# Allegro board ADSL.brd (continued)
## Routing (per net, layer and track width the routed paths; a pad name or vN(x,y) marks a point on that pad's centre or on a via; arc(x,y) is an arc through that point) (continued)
EJTAG_TDI: length 5.1
  TOP w0.152: U1.52 63.77,20.64 63.69,20.56 63.69,18.71 R388.2
EJTAG_TDO: length 6.6
  TOP w0.152: U1.49 62.27,17.42 R387.2 R365.2 R366.2
EJTAG_TMS: length 1.9
  TOP w0.152: R380.2 62.77,20.13 U1.50
EJTAG_TRST: length 4.8
  TOP w0.152: U1.51 63.27,20.7 63.39,20.59 63.39,18.53 63.88,18.03 R364.2
ETHERNET: length 46.2
  TOP w0.152: v2(57.02,3.3) 57.43,2.9 58.78,2.9 59.69,3.81 62.08,3.81 62.99,2.9 66.78,2.9 LED4.2 ; v2(55.63,22.35) 55.63,22.86 56.92,24.16 56.92,33.36 56.39,33.89 U1.16
  BOTTOM w0.152: v2(57.02,3.3) 57.02,4.7 56.26,5.46 56.26,21.72 v2(55.63,22.35)
FFRING: length 12.7
  TOP w0.254: R385.2 105.03,49.38 R381.2 ; R381.2 R382.2 ; R381.2 104.67,49.74 104.67,51.3 R427.1
  TOP w0.508: R427.1 104.8,52.39 104.8,53.11 103.8,54.1 100.71,54.1 100.32,54.5 T5.6
FFTIP: length 13.5
  TOP w0.254: R382.1 R381.1 ; R381.1 104.27,49.62 104.27,51.27 R428.1 ; R381.1 104.02,49.38 R384.2
  TOP w0.508: T5.7 98.62,54.36 99.53,53.44 103.53,53.44 104.14,52.83 104.14,52.42 R428.1
FL_A15: length 43.2
  TOP w0.152: U29.2 88.44,51.06 88.46,51.04 89.32,50.18 89.32,46.21 87.96,44.86 77.98,44.86 75.93,46.9 73.87,46.9 72.77,45.8 72.77,44.88 72.28,44.39 U1.112
FL_A16: length 43.2
  TOP w0.152: U29.1 88.94,66.74 88.74,66.55 88.74,51.47 89.62,50.59 89.62,45.98 88.2,44.55 77.85,44.55 75.81,46.6 74,46.6 73.15,45.75 73.15,44.83 72.97,44.65 72.78,44.46 U1.111
FL_A17: length 22.6
  TOP w0.152: U29.48 88.94,46.26 87.86,45.19 78.13,45.19 75.88,47.43 v2(74.3,47.43) ; U1.110 73.28,44.45 73.79,44.96 v2(73.79,45.47)
  BOTTOM w0.152: v2(74.3,47.43) 73.79,46.93 v2(73.79,45.47)
FL_A18: length 49.2
  TOP w0.152: U29.17 v2(80.93,62.45) ; U1.108 76.65,41.39 77.39,42.14 81.15,42.14 82.04,43.03 88.83,43.03 91.15,45.34 91.15,61.24 v2(90.92,61.47)
  BOTTOM w0.152: v2(90.92,61.47) 90.28,62.1 81.24,62.1 80.93,62.41 v2(80.93,62.45)
FL_A19: length 49.5
  TOP w0.152: U1.107 76.58,40.89 77.52,41.83 81.28,41.83 82.17,42.72 88.96,42.72 91.45,45.22 91.45,61.84 v2(91.06,62.23) ; v2(81.47,62.99) 81.43,63.03 U29.16
  BOTTOM w0.152: v2(81.47,62.99) 82.05,62.41 90.88,62.41 v2(91.06,62.23)
FL_A20: length 49.3
  TOP w0.152: U1.106 76.59,40.39 77.72,41.53 81.41,41.53 82.3,42.42 89.08,42.42 91.75,45.09 91.75,63.63 89.41,65.97 89.41,69.34 87.79,70.96 R415.1 85.08,70.97 R416.2
FL_A21: length 51.1
  TOP w0.152: U1.104 74.91,39.39 74.78,39.52 74.78,41.61 75.61,42.44 81.03,42.44 81.92,43.33 88.7,43.33 90.84,45.47 90.84,51.69 90.38,52.15 90.38,62.32 90.87,62.81 90.87,63.56 v2(90.42,64.01) ; v2(84.2,64.01) 83.68,64.53 83.68,66.03 84.43,66.78 U29.10
  BOTTOM w0.152: v2(90.42,64.01) 89.89,64.54 88.42,64.54 87.88,64.01 v2(84.2,64.01)
FL_A22: length 53.1
  TOP w0.152: v2(82.58,62.94) 82.58,63.26 82.57,63.27 82.57,66.44 82.94,66.81 U29.13 ; U1.102 74.89,38.39 74.48,38.81 74.48,41.76 75.46,42.75 80.9,42.75 81.79,43.64 88.58,43.64 90.54,45.6 90.54,51.31 90.08,51.77 90.08,62.87 v2(90.34,63.13)
  BOTTOM w0.152: v2(90.34,63.13) 89.93,62.71 82.8,62.71 v2(82.58,62.94)
FL_CS0: length 22.6
  TOP w0.152: v2(73.94,40.89) 73.39,40.34 73.39,39.77 73.85,39.31 73.85,35.49 74.46,34.89 U1.95 76.71,34.89 77.62,35.8 R373.2 R372.2 ; U29.26 77.93,46.41 v2(78.11,46.23)
  BOTTOM w0.152: v2(78.11,46.23) 78.11,41.54 77.47,40.89 v2(73.94,40.89)
FL_CS1: length 7.5
  TOP w0.152: U1.96 76.77,35.39 77.12,35.73 77.12,37.18 77.27,37.34 79.91,37.34 R389.2 R390.2
FL_RD_N/ND_RD_N: length 16.1
  TOP w0.152: U1.100 75.06,37.39 74.78,37.67 74.78,38.07 74.17,38.68 74.17,39.88 v2(73.92,40.12) ; v2(78.94,46.25) U29.28
  BOTTOM w0.152: v2(73.92,40.12) 74.26,40.46 77.47,40.46 78.42,41.41 78.42,45.74 v2(78.94,46.25)
FL_RD_WR_N/ND_WR_N: length 56.7
  TOP w0.152: U1.94 74.53,34.39 73.55,35.37 73.55,39.18 73.09,39.65 73.09,40.8 75.34,43.05 80.77,43.05 81.66,43.94 88.45,43.94 90.23,45.72 90.23,50.87 89.77,51.32 89.77,62.99 89.81,63.03 89.81,63.48 v2(89.28,64.01) ; v2(83.41,64.01) 83.38,64.04 83.38,66.23 83.93,66.79 U29.11
  BOTTOM w0.152: v2(83.41,64.01) 83.94,63.47 87.99,63.47 88.52,64.01 v2(89.28,64.01)
FLASH_RY/BY#: length 2.2
  TOP w0.152: U29.15 81.94,69.74 R419.1
GPIO1: length 48.9
  TOP w0.152: v2(59.88,3.24) 59.23,2.59 53.57,2.59 R367.2 R368.2 50.52,3.94 LED2.2 ; U1.14 56.68,34.89 57.58,33.99 v2(57.58,23.24)
  BOTTOM w0.152: v2(57.58,23.24) 56.9,22.56 56.9,5.97 57.66,5.21 58.93,5.21 59.88,4.26 v2(59.88,3.24)
GPIO13: length 76.8
  TOP w0.152: v2(74.42,35.78) 74.42,35.78 74.53,35.89 U1.97 ; v2(70.99,24) 71.83,24 72.64,24.82 72.64,33.05 71.63,34.06 v2(71.63,35.69) ; LED1.1 37.52,6.15 73.28,6.15 74.63,7.49 74.63,12.91 72.83,14.7 v2(72.83,15.02)
  BOTTOM w0.152: v2(70.99,24) 71.53,23.47 71.53,23.02 71.3,22.79 71.3,15.8 72.07,15.02 v2(72.83,15.02) ; v2(71.63,35.69) 71.72,35.78 v2(74.42,35.78)
GPIO24: length 72.9
  TOP w0.152: v2(73.59,14.97) 73.59,14.37 74.93,13.03 74.93,7.37 73.41,5.84 42.29,5.84 LED1.3 ; v2(71.44,24.62) 71.99,24.62 72.34,24.97 72.34,32.92 71.09,34.16 71.09,35.96 v2(71.68,36.55) ; v2(74.42,36.55) 74.58,36.39 U1.98
  BOTTOM w0.152: v2(74.42,36.55) v2(71.68,36.55) ; v2(71.44,24.62) 71.88,24.18 71.88,22.73 71.6,22.45 71.6,15.93 71.97,15.56 73.05,15.56 73.59,15.02 v2(73.59,14.97)
IS_BYTE: length 2.1
  TOP w0.152: U29.47 88.44,46.56 R418.1
POR_IN: length 14.5
  TOP w0.152: U1.91 76.83,32.89 77.18,33.24 81.5,33.24 83.19,34.92 83.19,36.32 83.95,37.08 85.63,37.08 R413.1 85.72,39.04 U30.2
POR_OUT: length 63.9
  TOP w0.152: R414.1 79.61,32.63 77.46,32.63 76.72,31.89 U1.89 74.92,31.89 74.55,32.26 74.55,33.91 73.24,35.21 73.24,39.06 72.78,39.52 72.78,40.93 75.21,43.36 80.65,43.36 81.54,44.25 88.32,44.25 89.93,45.85 89.93,50.74 89.27,51.39 v2(89.27,63.25) ; v2(83.31,63.25) 82.88,63.68 82.88,66.24 83.43,66.8 U29.12
  BOTTOM w0.152: v2(83.31,63.25) 83.39,63.17 89.2,63.17 v2(89.27,63.25)
RD+: length 57.9
  TOP w0.152: U1.31 53.54,26.39 53.34,26.58 49.87,26.58 47.05,29.4 43.12,29.4 36.63,35.89 36.63,53.07 31.04,58.66 31.04,63.68 31.62,64.26 33.4,64.26 33.62,64.48 R405.1 35.05,64.77 35.43,65.15 T4.6
RD-: length 56.1
  TOP w0.152: U1.30 50,26.89 47.18,29.71 43.24,29.71 36.93,36.01 36.93,53.2 31.34,58.79 31.34,62.71 31.72,63.09 33.39,63.09 33.62,62.87 R406.1 35.18,62.48 35.43,62.23 T4.8
RESET_DEFAULT: length 6.7
  TOP w0.152: R356.2 81.14,32.93 77.33,32.93 76.79,32.39 U1.90
RTX: length 2.2
  TOP w0.152: U1.36 53.7,23.89 R409.1
SD_ADDR0: length 37.6
  TOP w0.152: TP1.1 55.7,68.76 U28.21 55.7,66.24 54.9,65.44 U27.23 54.9,61.61 49.5,56.21 49.5,39.5 51.61,37.39 U1.9
SD_ADDR1: length 80.4
  TOP w0.152: U1.10 53.41,36.89 53.21,37.08 51.49,37.08 49.2,39.37 49.2,56.34 54.1,61.24 U27.24 54.1,65.41 v2(54.48,65.79) 54.9,66.21 U28.22 ; v2(75.31,68.45) 75.31,61.83 78.36,58.78 78.36,50.29 77.43,49.37 U29.25
  BOTTOM w0.152: v2(75.31,68.45) 74.7,69.06 57.76,69.06 v2(54.48,65.79)
SD_ADDR2: length 62.5
  TOP w0.152: v2(76.07,68.45) 76.56,67.97 U29.24 ; U1.11 53.4,36.39 53.01,36.78 51.36,36.78 48.9,39.25 48.9,56.46 53.3,60.87 U27.25 53.3,65.49 v2(53.59,65.79) 54.1,66.29 U28.23
  BOTTOM w0.152: v2(76.07,68.45) 75.16,69.37 57.18,69.37 v2(53.59,65.79)
SD_ADDR3: length 65
  TOP w0.152: U1.12 53.39,35.89 52.83,36.45 51.26,36.45 48.59,39.12 48.59,56.59 52.5,60.5 U27.26 52.5,65.46 v2(52.83,65.79) 53.3,66.26 U28.24 ; U29.23 77.93,69.09 77.81,69.22 v2(76.07,69.22)
  BOTTOM w0.152: v2(76.07,69.22) 75.62,69.67 56.72,69.67 v2(52.83,65.79)
SD_ADDR4: length 49.2
  TOP w0.152: v2(53.3,57.4) U28.27 53.3,55.21 52.5,54.41 U27.29 52.5,45.11 53.21,44.4 53.21,41.15 53.47,40.89 U1.2 ; v2(76.06,62.74) 76.06,64.5 78.44,66.88 U29.22
  BOTTOM w0.152: v2(76.06,62.74) 75.83,62.51 60.71,62.51 57.46,59.26 55.16,59.26 v2(53.3,57.4)
SD_ADDR5: length 47.8
  TOP w0.152: U29.21 78.94,66.93 76.96,64.96 76.96,62.87 v2(76.83,62.74) ; v2(54.1,57.4) U28.28 54.1,55.12 53.3,54.32 U27.30 53.3,44.82 54.28,43.84 U1.1
  BOTTOM w0.152: v2(54.1,57.4) 55.63,58.93 57.56,58.93 60.83,62.2 76.3,62.2 v2(76.83,62.74)
SD_ADDR6: length 46.7
  TOP w0.152: v2(77.6,62.74) 77.6,64.96 79.44,66.8 U29.20 ; v2(54.9,57.4) U28.29 54.9,55.16 54.1,54.36 U27.31 54.1,44.58 55.29,43.39 U1.144
  BOTTOM w0.152: v2(54.9,57.4) 56.02,58.52 57.71,58.52 61.09,61.9 76.76,61.9 v2(77.6,62.74)
SD_ADDR7: length 45.9
  TOP w0.152: v2(77.6,61.98) 78.11,62.48 78.11,62.49 78.13,62.52 78.13,64.87 79.93,66.67 U29.19 ; U1.143 56.77,44.1 54.9,45.97 U27.32 54.9,54.39 55.7,55.19 U28.30 v2(55.7,57.4)
  BOTTOM w0.152: v2(77.6,61.98) 77.22,61.59 61.22,61.59 57.84,58.22 56.52,58.22 v2(55.7,57.4)
SD_ADDR8: length 45.7
  TOP w0.152: U29.18 80.43,66.55 78.49,64.6 78.49,62.1 v2(78.36,61.98) ; v2(56.5,57.39) U28.31 56.5,55.36 55.7,54.56 U27.33 55.7,45.6 56.89,44.41 57.06,44.41 57.27,44.2 U1.142
  BOTTOM w0.152: v2(56.5,57.39) 57.02,57.91 57.96,57.91 61.34,61.29 77.67,61.29 v2(78.36,61.98)
SD_ADDR9: length 52
  TOP w0.152: U1.141 57.77,44.21 57.26,44.72 57.02,44.72 56.5,45.23 U27.34 56.5,54.6 57.3,55.4 U28.32 v2(57.3,57.38) ; v2(85.4,60.68) 85.44,60.71 U29.8
  BOTTOM w0.152: v2(85.4,60.68) 85.33,60.68 85.03,60.99 61.47,60.99 57.86,57.38 v2(57.3,57.38)
SD_ADDR10: length 71.1
  TOP w0.152: U29.7 v2(85.94,69.55) ; U1.8 51.54,37.89 49.81,39.63 49.81,56.08 55.7,61.98 U27.22 55.7,65.48 v2(56.01,65.79) 56.5,66.28 U28.20
  BOTTOM w0.152: v2(56.01,65.79) 58.98,68.76 74.19,68.76 75.81,67.13 85.63,67.13 85.94,67.44 v2(85.94,69.55)
SD_ADDR11: length 53.5
  TOP w0.152: v2(57.53,54.74) 57.3,54.51 U27.35 57.3,49.12 58.95,47.47 58.95,44.88 59.27,44.56 U1.138 ; U29.6 86.44,66.47 87,65.91 87,60.3 v2(86.84,60.15)
  BOTTOM w0.152: v2(86.84,60.15) 84.86,60.15 84.33,60.68 61.6,60.68 57.91,57 57.91,55.12 v2(57.53,54.74)
SD_ADDR12: length 53.7
  TOP w0.152: U1.137 59.77,44.49 59.26,45.01 59.26,47.68 58.1,48.83 U27.36 58.1,54.54 v2(58.29,54.73) ; v2(87.6,60.05) 87.6,65.74 86.93,66.41 U29.5
  BOTTOM w0.152: v2(87.6,60.05) 87.16,59.61 84.96,59.61 84.2,60.38 61.72,60.38 58.29,56.95 v2(58.29,54.73)
SD_BA0: length 34.3
  TOP w0.152: U28.19 U27.20 57.3,62.71 50.42,55.83 50.42,39.88 51.41,38.89 U1.6
SD_BA1: length 32.1
  TOP w0.152: U27.21 56.5,62.34 50.11,55.96 50.11,39.75 51.48,38.39 U1.7
SD_CAS_N_R: length 36
  TOP w0.152: U28.16 U27.17 59.7,63.36 63.83,59.23 70.27,59.23 73.24,56.27 73.24,52.43 66.27,45.47 U1.124
SD_CKE: length 13.3
  TOP w0.152: U1.136 60.27,44.43 59.56,45.14 59.56,50.9 R391.2 58.9,51.56 U27.37 U28.34
SD_CLK_O_R: length 10.5
  TOP w0.152: U28.35 U27.38 59.7,52.06 60.83,50.93 R431.1 60.83,46.07
SD_CS0_N: length 34
  TOP w0.152: U1.5 53.09,39.39 53.05,39.36 51.4,39.36 50.72,40.03 50.72,55.7 58.1,63.08 U27.19 U28.18
SD_DQ0: length 52.4
  TOP w0.152: U28.2 70.9,66.13 v2(71.25,65.79) 71.7,65.33 U27.2 71.7,62.12 76.29,57.53 76.29,51.17 71.28,46.16 U1.114 ; U29.29 79.44,57.11 79.02,57.53 v2(79.02,64.16)
  BOTTOM w0.152: v2(79.02,64.16) 78.99,64.16 78.77,64.39 74.68,64.39 73.28,65.79 v2(71.25,65.79)
SD_DQ1: length 55.2
  TOP w0.152: v2(79.77,64.26) 79.77,60.56 80.14,60.2 80.14,57.53 80.43,57.23 U29.31 ; U28.3 v2(70.1,65.79) U27.4 70.1,63.28 75.98,57.41 75.98,51.29 70.78,46.09 U1.115
  BOTTOM w0.152: v2(70.1,65.79) 70.64,66.32 73.18,66.32 74.8,64.69 79.35,64.69 v2(79.77,64.26)
SD_DQ2: length 58.8
  TOP w0.152: v2(80.39,64.77) 80.39,60.96 81.2,60.15 81.2,57.86 81.43,57.63 U29.33 ; U28.5 v2(68.5,65.79) 69.3,64.99 U27.5 69.3,63.65 75.68,57.28 75.68,51.42 70.28,46.02 U1.116
  BOTTOM w0.152: v2(68.5,65.79) 69.34,66.62 73.3,66.62 74.93,65 80.16,65 v2(80.39,64.77)
SD_DQ3: length 63.1
  TOP w0.152: U29.35 82.44,59.94 82.04,60.34 82.04,65.02 v2(82.04,65.02) ; U1.117 69.78,45.95 75.37,51.55 75.37,57.15 71.16,61.37 68.68,61.37 67.7,62.34 U27.7 v2(67.7,65.79) U28.6
  BOTTOM w0.152: v2(67.7,65.79) 68.85,66.93 73.43,66.93 75.06,65.3 81.76,65.3 v2(82.04,65.02)
SD_DQ4: length 68.4
  TOP w0.152: U28.8 66.1,66.56 v2(66.9,65.76) U27.8 66.9,62.38 68.22,61.06 71.03,61.06 75.07,57.03 75.07,51.67 69.28,45.88 U1.118 ; v2(84.22,65.33) 84.73,64.81 84.73,61.54 83.59,60.4 83.59,50.89 83.93,50.55 U29.38
  BOTTOM w0.152: v2(84.22,65.33) 83.93,65.61 75.18,65.61 73.56,67.23 67.61,67.23 66.9,66.52 v2(66.9,65.76)
SD_DQ5: length 70.7
  TOP w0.152: U28.9 v2(65.3,65.79) U27.10 65.3,63.22 67.77,60.76 70.91,60.76 74.76,56.9 74.76,51.8 68.78,45.81 U1.119 ; U29.40 84.94,50.93 84.71,51.15 84.71,61.09 85.09,61.47 85.09,65.47 v2(84.9,65.66)
  BOTTOM w0.152: v2(84.9,65.66) 84.65,65.91 75.31,65.91 73.68,67.54 67.06,67.54 v2(65.3,65.79)
SD_DQ6: length 74.1
  TOP w0.152: U1.120 68.27,45.74 74.46,51.93 74.46,56.77 70.78,60.45 67.31,60.45 64.5,63.26 U27.11 64.5,65.04 v2(63.75,65.79) 63.7,65.84 U28.11 ; v2(85.98,65.2) 85.94,65.16 U29.42
  BOTTOM w0.152: v2(85.98,65.2) 85.98,65.34 85.1,66.22 75.43,66.22 73.81,67.84 65.39,67.84 63.75,66.21 v2(63.75,65.79)
SD_DQ7: length 77.2
  TOP w0.152: v2(86,66.07) 86.51,65.56 86.51,64.15 86.31,63.95 86.31,58.73 87,58.03 87,50.16 86.93,50.1 U29.44 ; U28.12 v2(62.9,65.79) U27.13 62.9,62.95 65.71,60.15 70.65,60.15 74.15,56.65 74.15,52.05 67.77,45.68 U1.121
  BOTTOM w0.152: v2(62.9,65.79) 65.27,68.15 73.94,68.15 75.56,66.52 85.55,66.52 v2(86,66.07)
SD_DQ8: length 43.4
  TOP w0.152: v2(62.9,57.4) U28.39 U27.42 62.9,46.86 62.31,46.27 62.31,45.26 61.77,44.73 U1.133 ; v2(79.55,59.54) 79.55,57.66 79.93,57.28 U29.30
  BOTTOM w0.152: v2(79.55,59.54) 79.17,59.16 64.66,59.16 v2(62.9,57.4)
SD_DQ9: length 44.4
  TOP w0.152: v2(80.67,59.54) 80.67,57.66 80.93,57.39 U29.32 ; U1.132 62.27,44.62 62.78,45.12 62.78,46.03 64.5,47.75 U27.44 64.5,54.74 63.7,55.54 U28.40 v2(63.7,57.4)
  BOTTOM w0.152: v2(80.67,59.54) 79.98,58.85 65.15,58.85 v2(63.7,57.4)
SD_DQ10: length 42.2
  TOP w0.152: U1.131 62.77,44.61 63.12,44.96 63.12,45.85 65.3,48.03 U27.45 U28.42 65.3,57.15 v2(65.56,57.4) ; v2(81.9,58.55) 81.94,58.51 U29.34
  BOTTOM w0.152: v2(81.9,58.55) 66.7,58.55 v2(65.56,57.4)
SD_DQ11: length 43
  TOP w0.152: U1.130 63.27,44.6 63.47,44.8 63.47,45.56 65.66,47.75 65.66,50.83 66.9,52.07 U27.47 66.9,54.13 66.1,54.93 U28.43 66.1,56.96 v2(66.55,57.4) ; U29.36 82.94,58.26 v2(82.97,58.29)
  BOTTOM w0.152: v2(66.55,57.4) 67.39,58.24 81.45,58.24 81.68,58.01 82.69,58.01 v2(82.97,58.29)
SD_DQ12: length 42.3
  TOP w0.152: U1.129 63.77,45.44 65.96,47.63 65.96,50.6 67.7,52.34 U27.48 U28.45 v2(67.7,57.4) ; v2(84.12,58.04) 84.12,51.11 84.43,50.8 U29.39
  BOTTOM w0.152: v2(67.7,57.4) 68.24,57.94 81.33,57.94 81.55,57.71 83.79,57.71 v2(84.12,58.04)
SD_DQ13: length 39.5
  TOP w0.152: U1.128 64.27,45.22 69.3,50.25 U27.50 v2(69.3,54.78) 69.05,54.78 68.5,55.32 U28.46 ; U29.41 85.44,50.86 85.34,50.95 v2(85.34,56.01)
  BOTTOM w0.152: v2(69.3,54.78) 70.31,55.78 85.12,55.78 v2(85.34,56.01)
SD_DQ14: length 39.3
  TOP w0.152: U29.43 86.44,55.85 v2(86.47,55.88) ; U1.127 64.77,45.27 70.1,50.6 U27.51 v2(70.1,54.74) U28.48
  BOTTOM w0.152: v2(70.1,54.74) 70.84,55.47 86.03,55.47 86.44,55.88 v2(86.47,55.88)
SD_DQ15: length 40.1
  TOP w0.152: U28.49 70.9,54.95 v2(71.12,54.74) 71.7,54.15 U27.53 71.7,51.77 65.27,45.34 U1.126 ; v2(87.54,55.88) 87.43,55.78 U29.45
  BOTTOM w0.152: v2(71.12,54.74) 71.55,55.17 86.82,55.17 v2(87.54,55.88)
SD_DQM0: length 64.7
  TOP w0.152: U29.4 87.43,66.69 87.6,66.53 v2(87.6,66.5) ; U1.122 67.27,45.61 73.85,52.18 73.85,56.52 70.53,59.84 64.87,59.84 61.3,63.41 U27.15 v2(61.3,65.79) U28.14
  BOTTOM w0.152: v2(61.3,65.79) 63.97,68.45 74.06,68.45 75.69,66.83 87.27,66.83 v2(87.6,66.5)
SD_DQM1: length 53.4
  TOP w0.152: U1.134 61.27,44.66 62,45.39 62,51.27 60.5,52.77 U27.39 U28.36 v2(60.5,57.4) ; U29.3 87.93,67 88.13,66.8 88.13,59.54 v2(87.9,59.31)
  BOTTOM w0.152: v2(60.5,57.4) 60.5,58.72 61.85,60.07 84.07,60.07 84.84,59.31 v2(87.9,59.31)
SD_RAS_N_R: length 36.5
  TOP w0.152: U1.125 65.77,45.4 72.93,52.56 72.93,56.14 70.15,58.93 63.25,58.93 58.9,63.27 U27.18 U28.17
SD_WE_N: length 35.5
  TOP w0.152: U28.15 U27.16 60.5,63.32 64.29,59.54 70.4,59.54 73.54,56.4 73.54,52.31 66.77,45.54 U1.123
SPI_CLK: length 20.6
  TOP w0.152: U26.6 51.05,12.83 51.6,12.28 58.29,12.28 58.52,12.51 58.52,17.71 59.13,18.32 59.13,20.27 59.77,20.91 U1.44
SPI_CS1: length 15.2
  TOP w0.152: R422.1 58.29,10.29 59.44,11.43 59.44,17.32 60.02,17.91 61.59,17.91 61.97,18.29 61.97,20.84 61.77,21.03 U1.48
SPI_DIN: length 24.8
  TOP w0.152: v2(49.78,12.29) 51.07,11.01 58.05,11.01 59.13,12.09 59.13,17.44 59.9,18.21 60.81,18.21 61.48,18.88 61.48,20.89 61.27,21.1 U1.47 ; v2(49.78,13.59) 49.28,14.1 U26.5
  BOTTOM w0.152: v2(49.78,13.59) v2(49.78,12.29)
SPI_DOUT: length 15.2
  TOP w0.152: U1.45 60.27,20.9 59.44,20.07 59.44,18.2 58.83,17.59 58.83,12.22 58.17,11.56 U26.2
TD+: length 73.1
  TOP w0.152: U1.33 53.41,25.39 53.21,25.58 48.86,25.58 46.37,28.08 42.79,28.08 35.12,35.75 35.12,53.04 29.67,58.49 29.67,75.13 31.39,76.86 33.3,76.86 33.63,77.19 R403.2 34.92,77.47 35.43,77.98 T4.1
TD-: length 71.9
  TOP w0.152: T4.3 35.43,74.93 35.18,75.18 R404.2 33.63,75.59 33.43,75.79 30.84,75.79 29.97,74.93 29.97,58.62 35.43,53.17 35.43,35.87 42.91,28.38 46.49,28.38 48.99,25.89 U1.32
TP45: length 11.5
  TOP w0.508: R401.1 53.11,84.2 J9.A5 55.63,81.69 J9.A4
TP78: length 8.5
  TOP w0.508: J9.A8 51.82,81.69 J9.A7 51.72,83.06 R400.1
TPRXN: length 34
  BOTTOM w0.152: 43.05,61.09 44.2,62.23 44.2,63.07 44.45,63.32 45.08,63.32 45.59,63.83 45.59,73.28 50.42,78.11 56.06,78.11 57.15,79.2 57.15,81.15 57.66,81.66 59.05,81.66 59.31,81.41 59.31,80.77 58.96,80.42 J9.A2
TPRXP: length 33.2
  BOTTOM w0.152: 43.05,66.17 44.2,65.02 44.2,63.88 44.45,63.63 44.96,63.63 45.29,63.96 45.29,73.41 50.29,78.41 55.93,78.41 56.85,79.32 56.85,81.28 57.53,81.97 59.11,81.97 59.44,82.3 J9.A1
TPTXN: length 19.2
  BOTTOM w0.152: J9.A6 54.26,80.42 54.61,80.77 54.61,81.28 54.28,81.61 48.51,81.61 47.42,80.52 47.42,77.85 45.72,76.15 44.53,76.15 44.13,75.76 44.13,74.87 43.05,73.79
TPTXP: length 19.6
  BOTTOM w0.152: J9.A3 55.85,81.92 48.39,81.92 47.12,80.64 47.12,77.98 45.59,76.45 44.58,76.45 44.07,76.96 44.07,77.85 43.05,78.87
TRING: length 10.1
  TOP w0.254: D18.3 97.79,51.05 98.17,50.67 98.17,47.59 R425.1
  TOP w0.508: T5.8 96.39,54.86 D18.3
TTIP: length 10.5
  TOP w0.254: D19.3 99.06,51.05 98.58,50.57 98.58,47.56 R426.1
  TOP w0.508: D19.3 v2(100.33,52.2)
  BOTTOM w0.508: T5.5 100.33,53.69 v2(100.33,52.2)
UART_RX: length 15.3
  TOP w0.152: v2(48.51,35.56) 49.73,34.34 49.73,33.2 50.67,32.26 52.83,32.26 53.2,31.89 U1.20 ; R397.2 45.59,36.96 v2(44.96,36.32)
  BOTTOM w0.152: v2(48.51,35.56) 48.41,35.66 45.64,35.66 45.52,35.79 45.5,35.79 44.97,36.32 v2(44.96,36.32)
UART_TX: length 17.1
  TOP w0.152: v2(45.72,36.32) 46.1,36.7 46.1,41.55 R374.2 ; U1.19 53.21,32.39 53.04,32.56 50.88,32.56 50.03,33.4 50.03,34.8 v2(49.28,35.56)
  BOTTOM w0.152: v2(49.28,35.56) 48.74,36.09 45.95,36.09 v2(45.72,36.32)
USB: length 45.4
  TOP w0.152: v2(74.39,37.31) 74.58,37.31 75,36.89 U1.99 76.64,36.89 76.81,37.06 76.81,37.47 77.19,37.85 R371.2 R370.2 ; v2(74.36,14.99) 74.36,14.93 75.37,13.91 75.37,5.91 77.34,3.94 ; v2(71.75,25.4) 72.03,25.68 72.03,32.79 70.79,34.04 70.79,36.98 v2(71.12,37.31)
  BOTTOM w0.152: v2(71.75,25.4) 72.19,24.97 72.19,16.15 72.48,15.86 73.48,15.86 v2(74.36,14.99) ; v2(74.39,37.31) v2(71.12,37.31)
USB_DM: length 21.6
  TOP w0.152: R433.1 72.48,78.24 T6.3 73.16,77.56 76.34,77.56 76.64,77.87 76.64,77.92 ; J8.3 75.16,83.04 75.06,82.93 74.42,82.93 74.22,83.13 74.22,84.33 74.8,84.91 77.47,84.91 78.44,83.95 78.44,78.05 77.98,77.6 76.96,77.6 76.64,77.92 ; 76.64,77.92 D20.3
USB_DP: length 23.4
  TOP w0.152: J8.2 75.16,82.39 74.93,82.63 74.3,82.63 73.91,83.01 73.91,84.45 74.68,85.22 77.6,85.22 78.74,84.07 78.74,77.85 78.18,77.29 76.95,77.29 76.64,76.99 76.64,76.96 ; 76.64,76.96 D20.2 ; 76.64,76.96 76.34,77.26 73.04,77.26 T6.2 72.48,76.7 R434.1
USB_RREF: length 1.9
  TOP w0.152: U1.21 52.9,31.39 R392.1
VREF: length 2.2
  TOP w0.254: C355.2 56.27,20.83 U1.37
WAN_FFRING: length 52.1
  TOP w0.254: U1.79 97.43,26.89 100.43,29.89 100.43,47.14 v2(100.2,47.37) ; R427.2 v2(105.28,50.16)
  BOTTOM w0.254: v2(100.2,47.37) 100.46,47.62 100.46,49.53 101.73,50.8 104.65,50.8 v2(105.28,50.16)
WAN_FFTIP: length 50.4
  TOP w0.254: U1.78 77,26.39 77.09,26.48 97.6,26.48 100.6,29.48 100.84,29.72 100.84,47.12 v2(101.09,47.37) ; R428.2 v2(103.63,50.16)
  BOTTOM w0.254: v2(103.63,50.16) 103.4,50.39 101.9,50.39 100.86,49.36 100.86,47.6 v2(101.09,47.37)
WAN_HYBRING: length 52.2
  TOP w0.254: v2(105.03,36.7) 104.77,36.44 104.77,27.55 97.75,20.53 97.51,20.29 72.98,20.29 72.28,21 U1.69 ; v2(105.03,40.26) 105.12,40.35 C832.1 105.12,42.66 R430.2
  BOTTOM w0.254: v2(105.03,40.26) 104.8,40.03 104.8,36.93 v2(105.03,36.7)
WAN_HYBTIP: length 50.8
  TOP w0.254: v2(104.26,40.26) 104.15,40.37 C832.2 104.15,42.56 R429.2 ; v2(104.14,36.7) 104.36,36.48 104.36,27.72 97.34,20.7 73.15,20.7 72.78,21.08 U1.70
  BOTTOM w0.254: v2(104.26,40.26) 104.39,40.13 104.39,36.96 v2(104.14,36.7)
WAN_RRING: length 54.2
  TOP w0.254: C347.1 108.66,43.09 108.66,39.7 107.95,38.99 103.89,38.99 102.36,37.47 102.36,28.7 96.71,23.05 73.6,23.05 73.28,22.73 U1.71
  TOP w0.508: C347.1 108.08,43.7 R377.1
WAN_RTIP: length 53.9
  TOP w0.254: U1.72 73.78,22.38 74.04,22.64 96.88,22.64 102.77,28.53 102.77,37.24 104.11,38.58 108.12,38.58 109.07,39.53 109.07,43.14 C347.2
  TOP w0.508: R378.1 109.6,43.7 C347.2
WAN_TRING: length 51.2
  TOP w0.254: R425.2 98.17,45.87 98.17,45.34 v2(97.79,44.96) 98.17,44.58 98.17,30.73 96.83,29.39 76.96,29.39 ; R386.2 v2(106.68,44.96) ; 76.96,29.39 76.96,30.23 76.8,30.39 U1.86 ; 76.96,29.39 U1.84
  BOTTOM w0.254: v2(106.68,44.96) 106.05,44.32 98.42,44.32 v2(97.79,44.96)
WAN_TTIP: length 46
  TOP w0.254: U1.81 76.83,27.89 76.96,28.01 76.96,28.89 ; R383.2 v2(102.36,44.91) ; 76.96,28.89 77.06,28.98 97.05,28.98 98.58,30.51 98.58,44.55 v2(98.93,44.91) 98.58,45.26 98.58,45.9 R426.2 ; 76.96,28.89 U1.83
  BOTTOM w0.254: v2(98.93,44.91) v2(102.36,44.91)
WAN_XTAL1: length 12.2
  TOP w0.152: U1.59 67.27,20.83 67.44,20.67 67.44,15.66 C339.1 66.89,12.03 66.42,11.56 Y3.1
WAN_XTAL2: length 4.7
  TOP w0.152: R357.1 67.77,17.79 U1.60
N24553116: length 21.3
  TOP w0.533: J5.2 22.99,90.4 ; J5.2 20.13,89.03 ; J5.2 25.84,89.03 ; J5.2 22.99,87.66 ; 18.19,83.12 J5.3 ; J5.3 18.19,88.84 ; J5.3 16.82,85.98 ; J5.3 19.56,85.98 ; 23.24,76.88 C318.2 ; C318.2 23.83,77.58 ; C318.2 22.66,77.58 ; FB8.1 22.17,77.09 ; FB8.1 20.75,77.09 ; FB8.1 21.46,75.98
N24553123: length 11.5
  TOP w0.533: 20.13,82.93 J5.1 ; J5.1 22.99,81.56 ; J5.1 25.84,82.93 ; 22.66,79.13 C318.1 ; C318.1 23.24,79.84 ; C318.1 23.83,79.13 ; FB7.1 22.17,79.76 ; FB7.1 20.75,79.76 ; FB7.1 21.46,80.86
N24553218: length 12.3
  TOP w0.533: 16.05,79.13 C319.1 ; C319.1 17.22,79.13 ; C319.1 16.64,79.84 ; SW1.5 10.81,79.5 ; SW1.5 8.39,79.5 ; SW1.5 9.6,81.01 ; SW1.2 12.5,81.01 ; SW1.2 13.71,79.5 ; SW1.2 11.29,79.5 ; FB7.2 18.42,80.86 ; FB7.2 17.71,79.76 ; FB7.2 19.13,79.76
N24553231: length 14.9
  TOP w0.533: 17.04,72.9 D12.1 ; D12.1 19.79,72.9 ; D12.1 18.41,74.27 ; 16.64,76.88 C319.2 ; C319.2 17.22,77.58 ; C319.2 16.05,77.58 ; 22.23,71.53 D14.2 ; D14.2 20.85,72.9 ; D14.2 23.6,72.9 ; 17.71,77.09 FB8.2 18.42,75.98 ; R438.2 22.23,70.22 ; R438.2 21.26,69.22 ; R438.2 23.19,69.22
N24553775: length 2.9
  TOP w0.508: SW1.6 SW1.1
N24553814: length 17.6
  TOP w0.533: 6.45,66.55 D13.1 5.08,67.92 ; SW1.4 9.6,84.21 ; SW1.4 8.39,82.7 ; SW1.4 10.81,82.7 ; R437.1 8.76,67.51 ; R437.1 8.76,65.58 ; R437.1 7.76,66.55 ; SW1.3 12.5,84.21 ; SW1.3 11.29,82.7 ; SW1.3 13.71,82.7 ; D15.2 6.45,70.36 ; D15.2 5.08,71.73 ; D15.2 5.08,68.99
N24560058: length 19.6
  TOP w0.533: R437.2 11.56,67.51 ; R437.2 12.56,66.55 ; R437.2 11.56,65.58 ; D12.2 18.41,64.11 ; D12.2 18.41,61.37 ; D12.2 17.04,62.74 ; 11.56,61.77 R436.1 ; R436.1 11.56,63.7 ; R436.1 12.56,62.74 ; D13.2 16.61,66.55 ; D13.2 13.87,66.55 ; D13.2 15.24,65.18 ; 15.24,61.37 D23.1 ; D23.1 13.87,62.74 ; D23.1 15.24,64.11 ; D23.1 16.61,62.74
N24568861: length 11.3
  TOP w0.533: 14.91,51.38 Q305.3 14.14,50.42 ; 16.94,56.78 U11.7 15.78,56.26 ; R331.1 15.31,52.96 ; R331.1 14.73,52.25 ; R331.1 14.73,53.67 ; 15.31,56.26 R329.1 14.73,55.55 ; 15.67,53.21 R332.1 ; R332.1 16.38,54.13 ; R332.1 16.38,52.3 ; R330.1 15.31,54.61 ; R330.1 14.73,53.9 ; R330.1 14.73,55.32
N24570515: length 6.4
  TOP w0.533: R333.1 21.84,54.13 ; R333.1 21.84,52.3 ; R333.1 22.56,53.21 ; 21.78,54.99 U11.1 ; U11.1 22.94,54.47 ; U11.1 22.94,55.51 ; 18.09,54.99 U11.8 16.94,55.51
N24571646: length 6.8
  TOP w0.533: R333.2 20.07,54.13 ; R333.2 20.07,52.3 ; R333.2 19.35,53.21 ; 18.16,52.3 R332.2 ; R332.2 18.16,54.13 ; R332.2 18.87,53.21 ; 18.88,50.42 Q305.1 18.11,51.38
N24576177: length 3.3
  TOP w0.508: R336.2 25.06,56.4 C322.1 U11.3
N24577143: length 25.3
  TOP w0.508: R336.1 26,49.62 24.89,48.51 22.61,48.51
  TOP w0.533: 15.11,48.52 Q305.2 ; Q305.2 16.51,45.62 ; Q305.2 17.91,48.52 ; D16.2 20.83,49.89 ; D16.2 20.83,47.14 ; D16.2 22.2,48.51 ; D16.2 19.46,48.51 ; 15.02,39.75 L1.1 ; L1.1 17.33,39.75 ; L1.1 16.17,40.91
N24581993: length 2.6
  TOP w0.254: U11.5 16.94,60.14 R338.2 R337.2
N24591362: length 14
  TOP w0.533: R342.1 14.73,25.48 ; R342.1 14.73,24.05 ; R342.1 15.31,24.77 ; 14.73,25.7 R341.1 ; R341.1 14.73,27.13 ; R341.1 15.31,26.42 ; 15.67,26.92 R343.1 ; R343.1 16.38,26.01 ; R343.1 17.09,26.92 ; R343.1 16.38,27.84 ; 15.78,29.97 U12.7 16.94,30.49 ; 16.04,24.26 Q306.3 16.82,25.22 ; 14.73,29.01 R339.1 15.31,29.72 ; 14.73,27.36 R340.1 ; R340.1 15.31,28.07 ; R340.1 14.73,28.78
N24592746: length 7.5
  TOP w0.533: R343.2 18.87,26.92 ; R343.2 18.16,27.84 ; R343.2 18.16,26.01 ; 19.35,26.92 R344.2 ; R344.2 20.07,27.84 ; R344.2 20.07,26.01 ; R344.2 20.78,26.92 ; 20.01,25.22 Q306.1 20.79,24.26
N24593053: length 5.5
  TOP w0.533: 22.56,26.92 R344.1 21.84,27.84 ; 22.94,28.18 U12.1 ; U12.1 22.94,29.22 ; U12.1 21.78,28.7 ; 18.09,28.7 U12.8 16.94,29.22
N24596017: length 3.4
  TOP w0.508: U12.3 C327.1 25.06,29.99 R347.2
N24596365: length 24.1
  TOP w0.508: R347.1 26,24.73 23.88,22.61
  TOP w0.533: D17.2 22.61,21.31 ; D17.2 23.98,19.94 ; D17.2 22.61,18.57 ; D17.2 21.23,19.94 ; 18.41,19.45 Q306.2 ; Q306.2 17.01,22.36 ; Q306.2 19.82,22.36 ; L2.1 14.27,14.62 ; L2.1 14.27,12.31 ; L2.1 13.11,13.46 ; L2.1 15.42,13.46
N24598462: length 39.1
  TOP w0.254: R348.1 25.15,33.91 26.67,32.38 26.67,23.37 25.27,21.97 25.27,13.72
  TOP w0.533: 26.56,8.09 C328.1 27.05,8.57 ; 19.27,12.31 L2.2 ; L2.2 19.27,14.62 ; L2.2 20.42,13.46 ; 29.18,8.38 FB10.1 29.84,9.35 ; 28.19,8.57 C329.1 28.69,8.09 ; 25.25,11.71 CAP6.1 ; CAP6.1 27.58,11.71 ; CAP6.1 26.42,10.54 ; CAP6.1 26.42,12.88
N24599371: length 2.6
  TOP w0.254: U12.5 16.94,33.85 R349.2 R348.2
N24616723: length 5.3
  TOP w0.533: 30.1,30.2 U14.3 29.32,31.17 ; FB21.2 29.81,33.78 ; FB21.2 29.16,34.49 ; FB21.2 29.16,33.07 ; C331.1 28.79,32.63 ; C331.1 29.27,32.13 ; C331.1 28.79,31.64
N24643911: length 161.4
  TOP w0.152: v2(41.53,14.35) 41.53,8.04 42.67,6.9 72.56,6.9 73.78,8.13 73.78,12.74 71.41,15.11 v2(70.99,15.11) ; v2(70.99,23.24) 71.5,23.24 73.41,25.15 73.41,32.28 v2(73.89,32.77) ; S1.1 31.86,89.58 31.86,83.92 C340.2 30.21,83.81 29.72,83.31 29.72,77.47 27.94,75.69 27.94,57.53 32.64,52.83 32.64,35.81 41.53,26.92 v2(41.53,25.78) ; R412.1 R356.1 82.9,32.55 82.55,32.89 v2(82.17,32.89)
  BOTTOM w0.152: v2(70.99,23.24) v2(70.99,15.11) ; v2(41.53,14.35) v2(41.53,25.78) ; v2(73.89,32.77) 74.02,32.89 v2(82.17,32.89)
N24649929: length 12.1
  TOP w0.152: R397.1 45.56,40.51 J6.4 ; R435.2 J6.4 ; J6.4 42.42,41.66 40.84,41.66 39.87,42.63 39.87,44.56 J11.2
N24681692: length 6.4
  TOP w0.152: R357.2 68.24,16.37 C338.1 68.24,11.81 68.49,11.56 Y3.2
N24688074: length 2.8
  TOP w0.508: R361.2 65,4.21 LED4.1
N24688185: length 2.4
  TOP w0.508: LED5.1 74.53,4.21 R362.2
N24688407: length 2.9
  TOP w0.508: R360.2 55.48,4.21 LED3.1
N24690395: length 2.4
  TOP w0.508: R359.2 44.22,3.94 LED2.1
N24766052: length 4.7
  TOP w0.152: U1.67 71.28,20.67 71.49,20.46 71.49,17.63 R369.1
N24768447: length 9.5
  TOP w0.508: T5.4 104.99,54.1 108.08,54.1 108.46,53.72 108.46,51.96 C346.1 108.06,49.81 C348.2
N24768604: length 3.5
  TOP w0.508: T5.3 105.42,56.27 105.54,56.39 106.93,56.39 107.12,56.2 T5.2
N24769563: length 5.9
  TOP w0.508: C349.2 109.61,49.81 C346.2 109.12,52.06 109.12,54.06 108.83,54.36 T5.1
N24772143: length 1.5
  TOP w0.508: R377.2 C348.1
N24772316: length 1.5
  TOP w0.508: C349.1 R378.2
N24790501: length 7.1
  BOTTOM w0.762: C345.1 105.52,72.71 T5.14
N24791080: length 7.3
  BOTTOM w0.762: T5.11 100.22,72.2 C345.2
N24805096: length 31.1
  TOP w0.762: T5.9 100.39,72.06 RV2.2 ; J10.A3 100.39,84.01 RV2.2 ; RV2.2 RV1.2
  BOTTOM w0.762: C353.1 96.41,83.95 J10.A3
N24805705: length 36.9
  TOP w0.762: T5.16 104.84,72.56 RV2.1 ; J10.A4 100.83,87.12 102.49,87.12 104.84,84.77 RV2.1 ; RV2.1 RV1.1
  BOTTOM w0.762: C352.1 98.2,87.25 J10.A4
N24814618: length 3.5
  TOP w0.254: R386.1 105.33,46.7 C350.1 105.28,47.41 R385.1
N24814840: length 3.5
  TOP w0.254: R383.1 103.71,46.7 C351.1 103.76,47.53 R384.1
N24819336: length 1.6
  TOP w0.254: R430.1 105.16,45.07 C350.2
N24819791: length 1.7
  TOP w0.254: R429.1 104.01,44.95 C351.2
N24827024: length 1.9
  TOP w0.152: R431.2 60.77,45.18 U1.135
N24844121: length 3.3
  TOP w0.152: U29.14 82.44,69.63 R417.2 82.82,70.01 R416.1
N24844282: length 2.1
  TOP w0.152: U29.9 84.94,69.85 R415.2
N24965644: length 8.8
  TOP w0.508: R393.1 67.85,82.71 68.92,83.78 J8.4
N25062355: length 4.7
  TOP w0.152: J11.3 J6.3 45.56,43.05 R374.1
N25093250: length 1.7
  TOP w0.508: 43.05,76.33 44.68,76.33 R398.2
N25093296: length 9.7
  TOP w0.508: R399.2 44.2,72.16 44.2,64.77 43.05,63.63
N25094967: length 9.7
  TOP w0.508: R402.2 46.46,75.97 45.84,75.35 R398.1 R399.1
N25097039: length 26.6
  TOP w0.508: FB13.1 32.35,80.25 C344.2 36.08,80.25 36.58,79.76 36.58,76.33 ; R408.1 T4.7 35.94,63.63 36.58,64.26 36.58,76.33 ; R407.1 T4.2 36.58,76.33
N25099977: length 6.2
  TOP w0.508: v2(31.75,75.18) R404.1 32.67,74.04 C342.1 ; R403.1 v2(31.75,77.47) ; R407.2 v2(31.75,76.33)
  BOTTOM w0.508: v2(31.75,77.47) v2(31.75,76.33) v2(31.75,75.18)
N25100585: length 5.8
  TOP w0.508: C343.2 32.66,65.9 R405.2 31.9,64.77 v2(31.88,64.8) ; R408.2 v2(31.88,63.63) ; R406.2 v2(31.88,62.48)
  BOTTOM w0.508: v2(31.88,64.8) v2(31.88,63.63) v2(31.88,62.48)
N25501507: length 5.8
  TOP w0.508: R358.2 41.3,2.84 39.19,2.84 LED1.2
N25576572: length 2
  TOP w0.152: U26.7 46.26,11.56 R420.1
N25585764: length 2.1
  TOP w0.152: U26.3 R421.1
N25586045: length 2.1
  TOP w0.152: U26.1 R422.2
N25936981: length 8.3
  TOP w0.152: U30.3 85.73,41.34 D22.1 91.49,41.34 CAP23.1
N25958136: length 8.3
  TOP w0.152: CAP22.1 96.27,33.19 95.61,32.54 R376.2 90.78,32.54 Q304.1
N25963368: length 6.6
  TOP w0.152: CAP23.2 91.2,35.83 Q304.3 R375.2
N26013339: length 2
  TOP w0.152: U1.41 58.27,20.4 R432.2
N26031302: length 76.3
  TOP w0.152: R433.2 71.52,78.23 T6.4 70.94,77.65 70.1,77.65 69.55,77.09 69.55,72.39 68.71,71.55 51.56,71.55 50.11,70.1 50.11,60.32 47.13,57.34 47.13,34.9 48.46,33.57 48.46,30.04 50.12,28.39 U1.27
N26031664: length 75.3
  TOP w0.152: U1.26 53.47,28.89 53.27,28.69 50.25,28.69 48.77,30.17 48.77,33.7 47.44,35.03 47.44,57.22 50.42,60.2 50.42,69.98 51.69,71.25 68.83,71.25 69.85,72.26 69.85,76.96 70.23,77.34 70.89,77.34 T6.1 71.52,76.71 R434.2
N26189415: length 6
  TOP w0.508: C354.1 42.5,81.92 R402.1 45.5,83.05 R400.2 R401.2

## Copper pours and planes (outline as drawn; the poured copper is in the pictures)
3.3V_E on TOP: 41.66,25.02 41.66,21.97 41.91,21.72 48.9,21.72 49.28,21.34 49.28,19.56 49.4,19.43 52.45,19.43 52.58,19.56 52.58,21.59 52.45,21.72 51.82,21.72 49.66,23.88 47.12,23.88 45.85,25.15 41.78,25.15
+1V5 on TOP: 31.37,12.83 31.37,8.13 31.62,7.87 37.97,7.87 38.54,8.45 38.54,12.76 38.23,13.08 31.62,13.08
+3V3 on TOP: 28.07,28.45 28.07,22.23 28.45,21.84 41.15,21.84 41.4,22.1 41.4,24.64 40.77,25.27 36.96,25.27 36.7,25.53 36.7,28.45 36.45,28.7 33.27,28.7 33.02,28.96 33.02,31.11 32.77,31.37 31.24,31.37 30.99,31.11 30.99,28.96 30.73,28.7 28.32,28.7
+5V on TOP: 20.32,40.77 20.32,36.45 20.57,36.2 26.16,36.2 26.29,36.07 26.29,33.53 26.42,33.4 28.19,33.4 28.19,35.18 28.32,35.31 29.72,35.31 30.23,35.81 30.23,39.12 29.97,39.37 26.8,39.37 25.02,41.15 20.7,41.15
VDD_1.8V on TOP: 48.77,21.08 48.77,16.26 48.64,16.13 42.04,16.13 41.78,16.38 41.78,21.08 42.04,21.34 48.51,21.34
VIN on TOP: 3.68,64.39 3.68,58.93 6.99,55.63 6.99,21.34 7.49,20.83 10.79,20.83 11.3,21.34 11.3,23.75 11.56,24 13.34,24 13.46,24.13 13.46,30.48 13.59,30.61 14.86,30.61 15.11,30.86 17.02,30.86 17.14,30.99 17.14,31.75 17.02,31.88 11.56,31.88 11.3,32.13 11.3,51.31 11.43,51.44 13.08,51.44 13.59,51.94 13.59,56.77 13.72,56.9 14.86,56.9 15.11,57.15 17.4,57.15 17.53,57.28 17.53,58.17 17.4,58.29 10.79,58.29 9.53,59.56 9.53,64.39 9.27,64.64 3.94,64.64
N24553116 on TOP: 28.83,78.61 28.83,90.3 28.19,90.93 16.51,90.93 16.13,90.55 16.13,83.06 16.51,82.68 19.18,82.68 19.68,83.19 19.68,86.49 20.57,87.38 26.54,87.38 26.92,87 26.92,79.76 25.4,78.23 20.57,78.23 20.32,77.98 20.32,75.95 20.57,75.69 25.91,75.69
N24553123 on TOP: 20.07,83.95 20.07,79.38 20.57,78.87 24.89,78.87 26.16,80.14 26.16,83.95 25.91,84.2 20.32,84.2
N24553218 on TOP: 8.26,80.77 8.26,78.49 8.76,77.98 14.35,77.98 15.11,78.74 19.3,78.74 19.43,78.87 19.43,81.03 19.3,81.15 8.64,81.15
N24553231 on TOP: 15.88,77.98 15.88,72.14 16.51,71.5 20.32,71.5 20.7,71.12 20.7,68.71 20.95,68.45 23.5,68.45 23.88,68.83 23.88,73.91 23.5,74.3 19.43,74.3 19.05,74.68 19.05,77.98 18.92,78.11 16,78.11
N24553814 on TOP: 13.84,84.2 13.84,81.79 13.59,81.53 6.99,81.53 6.6,81.15 6.6,68.2 6.73,68.07 9.4,68.07 9.65,67.82 9.65,65.41 9.4,65.15 4.57,65.15 4.51,65.21 3.87,65.21 3.68,65.41 3.68,82.8 5.33,84.45 13.59,84.45
N24560058 on TOP: 10.79,67.56 10.79,61.34 11.05,61.09 19.3,61.09 19.68,61.47 19.68,67.44 19.43,67.69 10.92,67.69
N24568861 on TOP: 14.35,56.77 14.35,52.2 13.72,51.56 13.72,49.91 13.84,49.78 15.62,49.78 15.75,49.91 15.75,51.94 16,52.2 16.76,52.2 16.76,54.23 16.64,54.36 15.75,54.36 15.62,54.48 15.62,55.63 16,56.01 17.53,56.01 17.65,56.13 17.65,56.77 17.53,56.9 15.24,56.9 15.11,56.77
N24570515 on TOP: 16,55.63 16,54.86 16.13,54.74 21.34,54.74 21.46,54.61 21.46,52.32 21.59,52.2 23.75,52.2 23.88,52.32 23.88,55.63 23.75,55.75 16.13,55.75
N24571646 on TOP: 17.53,53.98 17.53,50.04 17.78,49.78 19.43,49.78 19.56,49.91 19.56,51.44 19.68,51.56 20.57,51.56 20.7,51.69 20.7,53.98 20.45,54.23 17.78,54.23
N24577143 on TOP: 22.86,49.53 22.86,44.83 22.35,44.32 18.54,44.32 17.91,43.69 17.91,38.86 17.65,38.61 13.84,38.61 13.59,38.86 13.59,49.02 13.72,49.15 19.3,49.15 20.32,50.16 22.23,50.16
N24591362 on TOP: 14.35,29.84 14.35,23.62 14.48,23.5 17.14,23.5 17.27,23.62 17.27,27.69 17.02,27.94 15.75,27.94 15.62,28.07 15.62,29.34 16,29.72 17.14,29.72 17.27,29.84 17.27,30.48 17.14,30.61 15.11,30.61
N24592746 on TOP: 17.78,27.81 17.78,26.04 17.91,25.91 19.3,25.91 19.43,25.78 19.43,23.62 19.56,23.5 20.7,23.5 20.95,23.75 20.95,27.81 20.7,28.07 18.03,28.07
N24593053 on TOP: 16,29.34 16,28.57 16.13,28.45 20.95,28.45 21.34,28.07 21.34,26.42 21.72,26.04 23.75,26.04 24,26.29 24,29.34 23.88,29.46 16.13,29.46
N24596365 on TOP: 24.38,22.48 24.38,18.54 23.88,18.03 16.26,18.03 15.75,17.53 15.75,12.06 15.37,11.68 12.7,11.68 12.32,12.06 12.32,22.48 12.76,22.92 15.3,22.92 15.37,22.99 23.88,22.99
N24598462 on TOP: 22.1,11.05 25.4,7.75 29.72,7.75 30.1,8.13 30.1,12.7 29.72,13.08 26.16,13.08 24,15.24 18.67,15.24 18.41,14.99 18.41,11.3 18.67,11.05
N24616723 on TOP: 28.57,34.54 28.57,29.72 28.83,29.46 30.35,29.46 30.61,29.72 30.61,34.54 30.35,34.8 28.83,34.8

Small or netless copper shapes (teardrops, artwork), in the pictures only: 24 on BOTTOM

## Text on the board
BOTTOM: BOTTOM SIDE
Ref Des/Assembly Bottom: ASSEMBLY BOTTOM
Board Geometry/Soldermask Bottom: SOLDERMASK BOTTOM
Ref Des/Silkscreen Bottom: SILKSCREEN BOTTOM
TOP: TOP SIDE | www.pcbb.com  The  PCB File share  QQ Group:562010407
Ref Des/Assembly Top: ASSEMBLY TOP
Board Geometry/Soldermask Top: SOLDERMASK TOP
Ref Des/Silkscreen Top: SILKSCREEN TOP
BODY_CENTER: 209052202200L | 209013200002L | P/N:209054000004L | 2090 | 209010711005L | 209011100005L | Power  Link | Data | Ethernet USB | 14mm | 13mm | 10mm | 16mm
FILM_FORMAT: Designated total thickness(include solder resist)  62+/-6mil | Trace width Tol. | via plating thickness | Thickness | Spacing Tol. | Impedance Tol. | V-Cut | Remaining Thk. | Angle | Tol. | Circuitry | Hole | PTH | NPTH | Plating slot hole | Layer | Solder Mask | Color | L1 | L2 | OSP Plating | 0.2-0.6um | Green | 0.4mil (min) - 1 mil (max) | 0.60 +/- 0.10mm | +/-20% | +/-10% | 30 +/- 5 deg. | +/- 0.15 mm | Cu finished | 1.4 | 0.8mil (min) | Tol. = +/-3mil | Tol. = +/-2mil | Tol. = +/-4mil | L1-L2 | Layer to | 44.2 | Material | FR4 | Unit: mil | Diel const. | 4.5 | BOARD THICKNESS:   1.6 | BOARD NAME: | LAYER: | DESIGNER: | E-MAIL: | SUPERCISOR: | ***@twsz.com | *** | ****** | REV: | LAYERS: | DATE: | TEL: | ** | YYYY-MM-DD | 0755-********
User.6: PASTE MASK TOP
User.7: PASTE MASK BOTTOM
